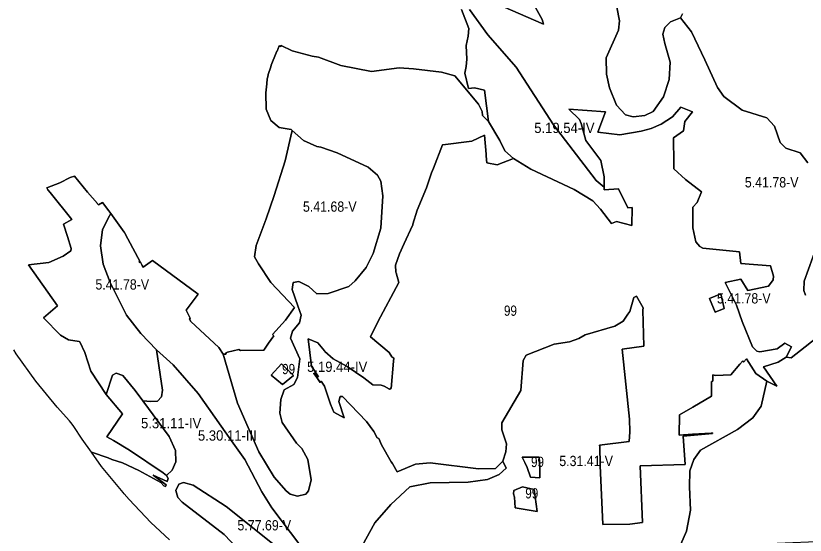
# Model space of a CAD drawing. Extents: x -591496 to -585489, y -1120610 to -1115685.
# Drawn here: x -590587 to -589052, y -1119649 to -1118638 of the extents above; entities that cross this region are included whole.
import ezdxf

# ---------------------------------------------------------------- set-up
doc = ezdxf.new("R2010")
doc.units = 0
doc.header["$LTSCALE"] = 8
doc.layers.add('40', color=7, linetype='Continuous', lineweight=25)
doc.layers.add('41', color=7, linetype='Continuous')

msp = doc.modelspace()

# ---------------------------------------------------------------- linework, layer by layer
at = {"layer": '40'}
for points in [[(-589586, -1118604), (-589563.5, -1118645), (-589561, -1118654.5), (-589684.5, -1118599.5)], [(-589684.5, -1118599.5), (-589561, -1118654.5), (-589563.5, -1118645), (-589586, -1118604)], [(-589720, -1118626), (-589706, -1118663), (-589707.5, -1118678), (-589711.5, -1118696), (-589710, -1118722.5), (-589711.5, -1118736.5), (-589713.5, -1118750), (-589706.5, -1118779.5), (-589695, -1118778.5), (-589675.5, -1118783), (-589667.5, -1118843.5), (-589678.796, -1118832.675), (-589679.511, -1118831.84), (-589680, -1118824.5), (-589687.5, -1118810), (-589733, -1118755), (-589759, -1118748), (-589813.5, -1118741), (-589841.5, -1118739.5), (-589895.5, -1118746.5), (-589955, -1118734.5), (-589998.5, -1118718.5), (-590010.5, -1118716.5), (-590049.5, -1118706), (-590071, -1118696), (-590072.361, -1118697.762), (-590074.98, -1118696.58), (-590079.198, -1118706.609), (-590079.5, -1118707), (-590080.716, -1118710.219), (-590090.81, -1118734.22), (-590090.945, -1118737.295), (-590096.5, -1118752), (-590097.104, -1118756.829), (-590098.58, -1118760.96), (-590098.833, -1118770.662), (-590101, -1118788), (-590100, -1118819.5), (-590091, -1118842), (-590075, -1118855.5), (-590052, -1118859.5), (-590049.613, -1118861.409), (-590050.059, -1118863.857), (-590063.5, -1118920.5), (-590084.5, -1118988), (-590100, -1119033.5), (-590119.5, -1119085), (-590123, -1119107.5), (-590115.5, -1119121), (-590091.5, -1119157), (-590045, -1119206), (-590062.957, -1119230.295), (-590088.22, -1119258.38), (-590085.456, -1119260.734), (-590096, -1119275), (-590104.752, -1119289.08), (-590150.46, -1119289.31), (-590153.81, -1119287.41), (-590175.23, -1119292.91), (-590179.63, -1119294.45), (-590178.088, -1119296.552), (-590184, -1119297), (-590192.5, -1119283.5), (-590247, -1119233), (-590249.332, -1119228.67), (-590248.1, -1119226.71), (-590255.692, -1119211.077), (-590232.5, -1119180), (-590321.5, -1119114.5), (-590339.475, -1119127.272), (-590341.6, -1119124.18), (-590345.08, -1119117.68), (-590346.375, -1119118.505), (-590347.552, -1119116.602), (-590346.15, -1119115.66), (-590349.85, -1119108.74), (-590374.39, -1119062.37), (-590375.21, -1119060.82), (-590376.42, -1119059), (-590402.728, -1119023.107), (-590406.61, -1119017.81)], [(-589705, -1118626), (-589669, -1118675), (-589614, -1118738), (-589541.5, -1118850.5), (-589458, -1118958.5), (-589443, -1118971.5), (-589443, -1118976.5), (-589415, -1118975), (-589396.5, -1119012), (-589388.5, -1119011.5), (-589389, -1119046.5), (-589418.5, -1119038.5), (-589428.5, -1119042.5), (-589450, -1119014.5), (-589465, -1118998.5), (-589501, -1118976), (-589585.5, -1118936.5), (-589619, -1118916), (-589636, -1118901), (-589645.5, -1118880.5), (-589667.5, -1118843.5), (-589675.5, -1118783), (-589695, -1118778.5), (-589706.5, -1118779.5), (-589713.5, -1118750), (-589711.5, -1118736.5), (-589710, -1118722.5), (-589711.5, -1118696), (-589707.5, -1118678), (-589706, -1118663), (-589720, -1118626)], [(-589308, -1118875.5), (-589288.5, -1118862), (-589286, -1118844), (-589271, -1118825), (-589293.5, -1118816), (-589310, -1118835), (-589332, -1118849), (-589351, -1118857.5), (-589370.5, -1118862.5), (-589412, -1118870), (-589455, -1118864.5), (-589440, -1118825), (-589511.5, -1118819.5), (-589491, -1118840), (-589487.5, -1118848), (-589478.5, -1118880.5), (-589449.5, -1118920), (-589442.5, -1118951.5), (-589443, -1118971.5), (-589458, -1118958.5), (-589541.5, -1118850.5), (-589614, -1118738), (-589669, -1118675), (-589705, -1118626)], [(-589290, -1118634), (-589294.5, -1118642), (-589313.5, -1118650), (-589325, -1118660.5), (-589328.5, -1118674), (-589324.5, -1118692), (-589314.5, -1118728), (-589316.5, -1118762), (-589327.5, -1118795.5), (-589347.5, -1118824.5), (-589363.5, -1118832), (-589386.5, -1118834.5), (-589401, -1118830.5), (-589418.5, -1118812), (-589432.5, -1118778.5), (-589438.5, -1118751.5), (-589439, -1118720), (-589415, -1118666), (-589413, -1118648), (-589418, -1118621)], [(-589418, -1118621), (-589413, -1118648), (-589415, -1118666), (-589439, -1118720), (-589438.5, -1118751.5), (-589432.5, -1118778.5), (-589418.5, -1118812), (-589401, -1118830.5), (-589386.5, -1118834.5), (-589363.5, -1118832), (-589347.5, -1118824.5), (-589327.5, -1118795.5), (-589316.5, -1118762), (-589314.5, -1118728), (-589324.5, -1118692), (-589328.5, -1118674), (-589325, -1118660.5), (-589313.5, -1118650), (-589294.5, -1118642)], [(-589046.5, -1118924.5), (-589061.5, -1118904.5), (-589089, -1118895.5), (-589100, -1118884.5), (-589111.5, -1118853), (-589126.5, -1118836.5), (-589174.5, -1118822), (-589210, -1118795), (-589222.5, -1118777.5), (-589247, -1118723.5), (-589273, -1118669.5), (-589294.5, -1118642), (-589290, -1118634)], [(-589294.5, -1118642), (-589273, -1118669.5), (-589247, -1118723.5), (-589222.5, -1118777.5), (-589210, -1118795), (-589174.5, -1118822), (-589126.5, -1118836.5), (-589111.5, -1118853), (-589100, -1118884.5), (-589089, -1118895.5), (-589061.5, -1118904.5), (-589046.5, -1118924.5)], [(-590404, -1119157.5), (-590417.5, -1119121.5), (-590422.5, -1119085.5), (-590419, -1119054), (-590405, -1119027.5), (-590402.728, -1119023.107), (-590376.42, -1119059), (-590375.21, -1119060.82), (-590374.39, -1119062.37), (-590349.85, -1119108.74), (-590346.15, -1119115.66), (-590347.552, -1119116.602), (-590346.375, -1119118.505), (-590345.08, -1119117.68), (-590341.6, -1119124.18), (-590339.475, -1119127.272), (-590321.5, -1119114.5), (-590232.5, -1119180), (-590255.692, -1119211.077), (-590248.1, -1119226.71), (-590249.332, -1119228.67), (-590247, -1119233), (-590192.5, -1119283.5), (-590184, -1119297), (-590156, -1119392), (-590114.5, -1119486.5), (-590085, -1119536), (-590061.5, -1119563), (-590053.5, -1119569.5), (-590039.5, -1119573), (-590023, -1119569.5), (-590018, -1119563), (-590013, -1119541.5), (-590019.5, -1119501.5), (-590031, -1119480.5), (-590041.5, -1119470), (-590069.5, -1119429.5), (-590073.5, -1119411.5), (-590072, -1119385), (-590065.5, -1119366), (-590046.5, -1119355.5), (-590039.5, -1119342), (-590034.5, -1119306), (-590053, -1119265.5), (-590049, -1119252), (-590035.5, -1119236), (-590032.5, -1119220.5), (-590038.5, -1119202.5), (-590049.5, -1119171), (-590047.5, -1119157.5), (-590036.5, -1119155), (-590017, -1119165), (-590002, -1119179.5), (-589979.5, -1119178.5), (-589939.5, -1119165), (-589927, -1119154), (-589906, -1119128), (-589892, -1119101), (-589877, -1119051.5), (-589873.5, -1118988.5), (-589877, -1118960), (-589883.5, -1118948.5), (-589902, -1118933), (-589962.5, -1118904.5), (-589994, -1118894), (-590002, -1118892.5), (-590027.5, -1118881), (-590049.5, -1118861.5), (-590049.613, -1118861.409), (-590052, -1118859.5), (-590075, -1118855.5), (-590091, -1118842), (-590100, -1118819.5), (-590101, -1118788), (-590098.833, -1118770.662), (-590098.58, -1118760.96), (-590097.104, -1118756.829), (-590096.5, -1118752), (-590090.945, -1118737.295), (-590090.81, -1118734.22), (-590080.716, -1118710.219), (-590079.5, -1118707), (-590079.198, -1118706.609), (-590074.98, -1118696.58), (-590072.361, -1118697.762), (-590071, -1118696), (-590049.5, -1118706), (-590010.5, -1118716.5), (-589998.5, -1118718.5), (-589955, -1118734.5), (-589895.5, -1118746.5), (-589841.5, -1118739.5), (-589813.5, -1118741), (-589759, -1118748), (-589733, -1118755), (-589687.5, -1118810), (-589680, -1118824.5), (-589679.511, -1118831.84), (-589678.796, -1118832.675), (-589667.5, -1118843.5)], [(-589857, -1119363.5), (-589852.796, -1119310.255), (-589852.18, -1119304.74), (-589855.544, -1119301.845), (-589861, -1119293.5), (-589897.347, -1119262.63), (-589883.35, -1119234.06), (-589841.98, -1119156.96), (-589847.625, -1119138.5), (-589848, -1119137), (-589849, -1119123.5), (-589840.817, -1119101.358), (-589831.512, -1119081.087), (-589815.5, -1119046.5), (-589815.266, -1119045.693), (-589814.87, -1119044.83), (-589814.675, -1119043.651), (-589806.701, -1119016.131), (-589788.32, -1118972.91), (-589778.802, -1118943.68), (-589775, -1118934.5), (-589757.026, -1118889.067), (-589756.725, -1118888.966), (-589700.5, -1118882), (-589675.5, -1118870.5), (-589672.379, -1118907.607), (-589671.95, -1118921.28), (-589671.222, -1118921.356), (-589671, -1118924), (-589651, -1118928), (-589619, -1118916), (-589585.5, -1118936.5), (-589501, -1118976), (-589465, -1118998.5), (-589450, -1119014.5), (-589428.5, -1119042.5), (-589418.5, -1119038.5), (-589389, -1119046.5), (-589388.5, -1119011.5), (-589396.5, -1119012), (-589415, -1118975), (-589443, -1118976.5), (-589443, -1118971.5), (-589442.5, -1118951.5), (-589449.5, -1118920), (-589478.5, -1118880.5), (-589487.5, -1118848), (-589491, -1118840), (-589511.5, -1118819.5), (-589440, -1118825), (-589455, -1118864.5), (-589412, -1118870), (-589370.5, -1118862.5), (-589351, -1118857.5), (-589332, -1118849), (-589310, -1118835), (-589293.5, -1118816), (-589271, -1118825), (-589286, -1118844), (-589288.5, -1118862), (-589308, -1118875.5), (-589307, -1118925), (-589307, -1118936), (-589284.5, -1118956.5), (-589253.5, -1118981), (-589262, -1119001.5), (-589270, -1119010.5), (-589270.5, -1119051), (-589264.5, -1119078), (-589256.5, -1119087), (-589251, -1119090.5), (-589179.5, -1119097.5), (-589177, -1119120), (-589119, -1119124.5), (-589113.5, -1119145), (-589114, -1119152), (-589123, -1119164.5), (-589163.5, -1119173), (-589177, -1119151), (-589207, -1119157.5), (-589185.5, -1119201.5), (-589174, -1119233), (-589154, -1119282.5), (-589146, -1119291), (-589140, -1119292), (-589106, -1119286), (-589091.5, -1119275.5), (-589078.5, -1119282.5), (-589088.5, -1119302.5)], [(-589667.5, -1118843.5), (-589645.5, -1118880.5), (-589636, -1118901), (-589619, -1118916), (-589651, -1118928), (-589671, -1118924), (-589671.222, -1118921.356), (-589671.95, -1118921.28), (-589672.379, -1118907.607), (-589675.5, -1118870.5), (-589700.5, -1118882), (-589756.725, -1118888.966), (-589757.026, -1118889.067), (-589775, -1118934.5), (-589778.802, -1118943.68), (-589788.32, -1118972.91), (-589806.701, -1119016.131), (-589814.675, -1119043.651), (-589814.87, -1119044.83), (-589815.266, -1119045.693), (-589815.5, -1119046.5), (-589831.512, -1119081.087), (-589840.817, -1119101.358), (-589849, -1119123.5), (-589848, -1119137), (-589847.625, -1119138.5), (-589841.98, -1119156.96), (-589883.35, -1119234.06), (-589897.347, -1119262.63), (-589861, -1119293.5), (-589855.544, -1119301.845), (-589852.18, -1119304.74), (-589852.796, -1119310.255), (-589857, -1119363.5), (-589858.685, -1119362.938), (-589858.91, -1119364.95), (-589860.57, -1119364.94), (-589871.048, -1119358.817), (-589876.863, -1119356.879), (-589892.92, -1119356.33), (-589909.98, -1119342.589), (-589942.708, -1119320.455), (-589970.18, -1119305.68), (-589986.03, -1119291.28), (-589986.049, -1119291.143), (-589987, -1119290.5), (-590000, -1119274.5), (-590018.53, -1119267.147), (-590012.06, -1119320.12), (-589998.55, -1119340.86), (-590007.51, -1119333.92), (-590007.886, -1119334.386), (-590001.5, -1119342), (-589995.49, -1119351.533), (-589993.21, -1119349.05), (-589986.79, -1119358.9), (-589977.39, -1119388.225), (-589975, -1119394), (-589968.5, -1119409.5), (-589948.5, -1119420.5), (-589959, -1119389), (-589956.5, -1119379), (-589951.5, -1119379), (-589905, -1119428), (-589891, -1119447.5), (-589884.107, -1119459.391), (-589881.2, -1119461), (-589876.156, -1119473.11), (-589857.084, -1119506.015), (-589854.65, -1119509.64), (-589854.17, -1119511.041), (-589845.5, -1119526), (-589809.5, -1119511), (-589781, -1119508), (-589687, -1119520), (-589654, -1119519), (-589640, -1119505), (-589633.5, -1119518.5), (-589647, -1119531), (-589670, -1119540.5), (-589707, -1119546), (-589781, -1119547), (-589820.5, -1119555), (-589858, -1119589), (-589889, -1119625), (-589913.5, -1119670)], [(-589012, -1119251), (-589079, -1119304), (-589088.5, -1119302.5), (-589078.5, -1119282.5), (-589091.5, -1119275.5), (-589106, -1119286), (-589140, -1119292), (-589146, -1119291), (-589154, -1119282.5), (-589174, -1119233), (-589185.5, -1119201.5), (-589207, -1119157.5), (-589177, -1119151), (-589163.5, -1119173), (-589123, -1119164.5), (-589114, -1119152), (-589113.5, -1119145), (-589119, -1119124.5), (-589177, -1119120), (-589179.5, -1119097.5), (-589251, -1119090.5), (-589256.5, -1119087), (-589264.5, -1119078), (-589270.5, -1119051), (-589270, -1119010.5), (-589262, -1119001.5), (-589253.5, -1118981), (-589284.5, -1118956.5), (-589307, -1118936), (-589307, -1118925), (-589308, -1118875.5)], [(-590406.61, -1119017.81), (-590418.78, -1119001.7), (-590426.522, -1119005.978), (-590429.028, -1119003.472), (-590428.57, -1119003.21), (-590447.617, -1118981.388), (-590473, -1118950.5), (-590481.5, -1118952.5), (-590501.731, -1118963.075), (-590510.05, -1118966.23), (-590527.08, -1118972.62), (-590524.91, -1118976.64), (-590520.401, -1118981.955), (-590478.665, -1119034.791), (-590494.88, -1119043.75), (-590486.533, -1119067.38), (-590480, -1119091), (-590480.5, -1119095.5), (-590495.5, -1119106), (-590523, -1119118), (-590563, -1119123), (-590506, -1119202.5), (-590533.5, -1119226), (-590500.5, -1119259.5), (-590485, -1119269), (-590464.363, -1119271.814), (-590462.597, -1119272.867), (-590453, -1119293.5), (-590441.5, -1119329.5), (-590411.5, -1119375), (-590380, -1119412.5), (-590410, -1119457.5), (-590397.5, -1119464.5), (-590366, -1119483.5), (-590300.5, -1119527.5), (-590294, -1119533), (-590291, -1119538.5), (-590292.901, -1119544.585), (-590320.08, -1119532.32), (-590294.973, -1119551.214), (-590296, -1119554.5), (-590299.282, -1119552.785), (-590304.95, -1119546.61), (-590348.36, -1119523.25), (-590380.08, -1119508.2), (-590400.352, -1119501.759), (-590407.5, -1119498.5), (-590440.181, -1119487.607), (-590458.48, -1119462.07), (-590474.227, -1119437.746), (-590477.743, -1119433.191), (-590483.035, -1119426.232), (-590506.88, -1119399.996), (-590548.393, -1119349.411), (-590586.51, -1119296.22), (-590591.55, -1119288.115)], [(-589028.5, -1119084.5), (-589053.5, -1119154.5), (-589054.5, -1119172.5), (-589051, -1119182)], [(-589051, -1119182), (-589054.5, -1119172.5), (-589053.5, -1119154.5), (-589028.5, -1119084.5)], [(-590035, -1119668), (-590089, -1119596), (-590108.5, -1119564.5), (-590141.5, -1119501.5), (-590167.5, -1119465.5), (-590232.5, -1119373), (-590281, -1119317.5), (-590313.5, -1119288), (-590344, -1119256.5), (-590372, -1119220.5), (-590404, -1119157.5)], [(-589088.5, -1119302.5), (-589104, -1119312), (-589132.5, -1119321.5), (-589107, -1119359), (-589126.5, -1119349.5), (-589147.5, -1119334.5), (-589165.5, -1119305.5), (-589171.64, -1119312.057), (-589173.09, -1119309.83), (-589178.78, -1119316.45), (-589196.503, -1119337.049), (-589226, -1119338), (-589231.5, -1119337), (-589231.553, -1119349.125), (-589233.82, -1119349.83), (-589234.1, -1119378.75), (-589270.43, -1119399.89), (-589296.34, -1119414.97), (-589296.52, -1119454.44), (-589270.94, -1119452.55), (-589234.8, -1119450.31), (-589231.996, -1119450.106), (-589232, -1119451), (-589289, -1119456.5), (-589285, -1119511.5), (-589372.5, -1119514), (-589368, -1119624.5), (-589393, -1119627.5), (-589445.5, -1119628), (-589450.339, -1119513.362), (-589451.28, -1119474.97), (-589451.954, -1119475.086), (-589452, -1119474), (-589394, -1119466.5), (-589393, -1119448), (-589393.5, -1119423.5), (-589407.5, -1119287), (-589365.5, -1119281), (-589367.5, -1119211), (-589367, -1119206.5), (-589379.5, -1119183.5), (-589385, -1119186.5), (-589392.5, -1119213.5), (-589396.5, -1119219), (-589405.5, -1119232.5), (-589422, -1119242), (-589479.5, -1119259), (-589492, -1119266.5), (-589510, -1119272.5), (-589540, -1119277.5), (-589594.5, -1119298.5), (-589600, -1119309), (-589605, -1119367.5), (-589642, -1119430.5), (-589642, -1119444), (-589632.5, -1119471), (-589634, -1119486.5), (-589640, -1119505), (-589654, -1119519), (-589687, -1119520), (-589781, -1119508), (-589809.5, -1119511), (-589845.5, -1119526), (-589854.17, -1119511.041), (-589854.65, -1119509.64), (-589857.084, -1119506.015), (-589876.156, -1119473.11), (-589881.2, -1119461), (-589884.107, -1119459.391), (-589891, -1119447.5), (-589905, -1119428), (-589951.5, -1119379), (-589956.5, -1119379), (-589959, -1119389), (-589948.5, -1119420.5), (-589968.5, -1119409.5), (-589975, -1119394), (-589977.39, -1119388.225), (-589986.79, -1119358.9), (-589993.21, -1119349.05), (-589995.49, -1119351.533), (-590001.5, -1119342), (-590007.886, -1119334.386), (-590007.51, -1119333.92), (-589998.55, -1119340.86), (-590012.06, -1119320.12), (-590018.53, -1119267.147), (-590000, -1119274.5), (-589987, -1119290.5), (-589986.049, -1119291.143), (-589986.03, -1119291.28), (-589970.18, -1119305.68), (-589942.708, -1119320.455), (-589909.98, -1119342.589), (-589892.92, -1119356.33), (-589876.863, -1119356.879), (-589871.048, -1119358.817), (-589860.57, -1119364.94), (-589858.91, -1119364.95), (-589858.685, -1119362.938), (-589857, -1119363.5)], [(-589913.5, -1119670), (-589889, -1119625), (-589858, -1119589), (-589820.5, -1119555), (-589781, -1119547), (-589707, -1119546), (-589670, -1119540.5), (-589647, -1119531), (-589633.5, -1119518.5), (-589640, -1119505), (-589634, -1119486.5), (-589632.5, -1119471), (-589642, -1119444), (-589642, -1119430.5), (-589605, -1119367.5), (-589600, -1119309), (-589594.5, -1119298.5), (-589540, -1119277.5), (-589510, -1119272.5), (-589492, -1119266.5), (-589479.5, -1119259), (-589422, -1119242), (-589405.5, -1119232.5), (-589396.5, -1119219), (-589392.5, -1119213.5), (-589385, -1119186.5), (-589379.5, -1119183.5), (-589367, -1119206.5), (-589367.5, -1119211), (-589365.5, -1119281), (-589407.5, -1119287), (-589393.5, -1119423.5), (-589393, -1119448), (-589394, -1119466.5), (-589452, -1119474), (-589451.954, -1119475.086), (-589451.28, -1119474.97), (-589450.339, -1119513.362), (-589445.5, -1119628), (-589393, -1119627.5), (-589368, -1119624.5), (-589372.5, -1119514), (-589285, -1119511.5), (-589289, -1119456.5), (-589232, -1119451), (-589231.996, -1119450.106), (-589234.8, -1119450.31), (-589270.94, -1119452.55), (-589296.52, -1119454.44), (-589296.34, -1119414.97), (-589270.43, -1119399.89), (-589234.1, -1119378.75), (-589233.82, -1119349.83), (-589231.553, -1119349.125), (-589231.5, -1119337), (-589226, -1119338), (-589196.503, -1119337.049), (-589178.78, -1119316.45), (-589173.09, -1119309.83), (-589171.64, -1119312.057), (-589165.5, -1119305.5), (-589147.5, -1119334.5), (-589126.5, -1119349.5), (-589137.5, -1119398), (-589153.5, -1119420.5), (-589183.5, -1119443), (-589255, -1119483.5), (-589268.5, -1119501.5), (-589276, -1119524), (-589276.5, -1119555), (-589274.5, -1119600.5), (-589282.5, -1119641), (-589304.495, -1119691.988)], [(-588953.5, -1119659), (-589167, -1119667.5), (-589213, -1119678), (-589246, -1119686.5), (-589270.5, -1119690), (-589304.495, -1119691.988), (-589282.5, -1119641), (-589274.5, -1119600.5), (-589276.5, -1119555), (-589276, -1119524), (-589268.5, -1119501.5), (-589255, -1119483.5), (-589183.5, -1119443), (-589153.5, -1119420.5), (-589137.5, -1119398), (-589126.5, -1119349.5), (-589107, -1119359), (-589132.5, -1119321.5), (-589104, -1119312), (-589088.5, -1119302.5), (-589079, -1119304), (-589012, -1119251)], [(-590288.534, -1119658.177), (-590324.527, -1119624.467), (-590366.996, -1119579.278), (-590376.586, -1119568.418), (-590378.85, -1119565.846), (-590420.363, -1119515.261), (-590440.181, -1119487.607), (-590407.5, -1119498.5), (-590400.352, -1119501.759), (-590380.08, -1119508.2), (-590348.36, -1119523.25), (-590304.95, -1119546.61), (-590299.282, -1119552.785), (-590296, -1119554.5), (-590294.973, -1119551.214), (-590320.08, -1119532.32), (-590292.901, -1119544.585), (-590291, -1119538.5), (-590294, -1119533), (-590283.5, -1119522.5), (-590276, -1119506.5), (-590277, -1119484), (-590289, -1119457), (-590340.59, -1119387.567), (-590324.5, -1119389), (-590311.5, -1119388), (-590304, -1119380), (-590302, -1119366.5), (-590313.5, -1119288), (-590281, -1119317.5), (-590232.5, -1119373), (-590167.5, -1119465.5), (-590141.5, -1119501.5), (-590108.5, -1119564.5), (-590089, -1119596), (-590035, -1119668)], [(-590088, -1119665.5), (-590178, -1119593.5), (-590242.5, -1119551.5), (-590261, -1119546.5), (-590270, -1119549.5), (-590276, -1119562), (-590272.5, -1119575.5), (-590264, -1119585), (-590182, -1119647.5), (-590157, -1119674.5)]]:
    msp.add_lwpolyline(points, dxfattribs=at)
for points in [[(-590184, -1119297), (-590178.088, -1119296.552), (-590179.63, -1119294.45), (-590175.23, -1119292.91), (-590153.81, -1119287.41), (-590150.46, -1119289.31), (-590104.752, -1119289.08), (-590096, -1119275), (-590085.456, -1119260.734), (-590088.22, -1119258.38), (-590062.957, -1119230.295), (-590045, -1119206), (-590091.5, -1119157), (-590115.5, -1119121), (-590123, -1119107.5), (-590119.5, -1119085), (-590100, -1119033.5), (-590084.5, -1118988), (-590063.5, -1118920.5), (-590050.059, -1118863.857), (-590049.613, -1118861.409), (-590049.5, -1118861.5), (-590027.5, -1118881), (-590002, -1118892.5), (-589994, -1118894), (-589962.5, -1118904.5), (-589902, -1118933), (-589883.5, -1118948.5), (-589877, -1118960), (-589873.5, -1118988.5), (-589877, -1119051.5), (-589892, -1119101), (-589906, -1119128), (-589927, -1119154), (-589939.5, -1119165), (-589979.5, -1119178.5), (-590002, -1119179.5), (-590017, -1119165), (-590036.5, -1119155), (-590047.5, -1119157.5), (-590049.5, -1119171), (-590038.5, -1119202.5), (-590032.5, -1119220.5), (-590035.5, -1119236), (-590049, -1119252), (-590053, -1119265.5), (-590034.5, -1119306), (-590039.5, -1119342), (-590046.5, -1119355.5), (-590065.5, -1119366), (-590072, -1119385), (-590073.5, -1119411.5), (-590069.5, -1119429.5), (-590041.5, -1119470), (-590031, -1119480.5), (-590019.5, -1119501.5), (-590013, -1119541.5), (-590018, -1119563), (-590023, -1119569.5), (-590039.5, -1119573), (-590053.5, -1119569.5), (-590061.5, -1119563), (-590085, -1119536), (-590114.5, -1119486.5), (-590156, -1119392)], [(-590402.728, -1119023.107), (-590405, -1119027.5), (-590419, -1119054), (-590422.5, -1119085.5), (-590417.5, -1119121.5), (-590404, -1119157.5), (-590372, -1119220.5), (-590344, -1119256.5), (-590313.5, -1119288), (-590302, -1119366.5), (-590304, -1119380), (-590311.5, -1119388), (-590324.5, -1119389), (-590340.59, -1119387.567), (-590355.5, -1119367.5), (-590379, -1119338), (-590392, -1119333.5), (-590399.5, -1119337.5), (-590411.5, -1119375), (-590441.5, -1119329.5), (-590453, -1119293.5), (-590462.597, -1119272.867), (-590464.363, -1119271.814), (-590485, -1119269), (-590500.5, -1119259.5), (-590533.5, -1119226), (-590506, -1119202.5), (-590563, -1119123), (-590523, -1119118), (-590495.5, -1119106), (-590480.5, -1119095.5), (-590480, -1119091), (-590486.533, -1119067.38), (-590494.88, -1119043.75), (-590478.665, -1119034.791), (-590520.401, -1118981.955), (-590524.91, -1118976.64), (-590527.08, -1118972.62), (-590510.05, -1118966.23), (-590501.731, -1118963.075), (-590481.5, -1118952.5), (-590473, -1118950.5), (-590447.617, -1118981.388), (-590428.57, -1119003.21), (-590429.028, -1119003.472), (-590426.522, -1119005.978), (-590418.78, -1119001.7), (-590406.61, -1119017.81)], [(-589209, -1119208), (-589215.5, -1119179.5), (-589237.5, -1119188), (-589227, -1119215)], [(-589209, -1119208), (-589227, -1119215), (-589237.5, -1119188), (-589215.5, -1119179.5)], [(-590047, -1119338.5), (-590068.327, -1119355.726), (-590090.54, -1119337.84), (-590070.791, -1119315.642)], [(-590047, -1119338.5), (-590070.791, -1119315.642), (-590090.54, -1119337.84), (-590068.327, -1119355.726)], [(-590340.59, -1119387.567), (-590289, -1119457), (-590277, -1119484), (-590276, -1119506.5), (-590283.5, -1119522.5), (-590294, -1119533), (-590300.5, -1119527.5), (-590366, -1119483.5), (-590397.5, -1119464.5), (-590410, -1119457.5), (-590380, -1119412.5), (-590411.5, -1119375), (-590399.5, -1119337.5), (-590392, -1119333.5), (-590379, -1119338), (-590355.5, -1119367.5)], [(-589568.09, -1119517.13), (-589567.57, -1119537.53), (-589586.104, -1119535.837), (-589592.5, -1119517.5), (-589597, -1119507.5), (-589602.5, -1119497), (-589569.5, -1119497), (-589568.062, -1119517.125)], [(-589568.09, -1119517.13), (-589568.062, -1119517.125), (-589569.5, -1119497), (-589602.5, -1119497), (-589597, -1119507.5), (-589592.5, -1119517.5), (-589586.104, -1119535.837), (-589567.57, -1119537.53)], [(-590063.5, -1119719), (-590078, -1119728), (-590102.5, -1119733), (-590122.567, -1119727.234), (-590157, -1119674.5), (-590182, -1119647.5), (-590264, -1119585), (-590272.5, -1119575.5), (-590276, -1119562), (-590270, -1119549.5), (-590261, -1119546.5), (-590242.5, -1119551.5), (-590178, -1119593.5), (-590088, -1119665.5), (-590067, -1119692.5), (-590062.5, -1119706)], [(-589579, -1119560), (-589573, -1119603), (-589616, -1119595.5), (-589617, -1119575), (-589619.389, -1119568.63), (-589618.784, -1119561.914), (-589601.5, -1119555)], [(-589579, -1119560), (-589601.5, -1119555), (-589618.784, -1119561.914), (-589619.389, -1119568.63), (-589617, -1119575), (-589616, -1119595.5), (-589573, -1119603)]]:
    msp.add_lwpolyline(points, close=True, dxfattribs=at)

# ---------------------------------------------------------------- texts
at = {"layer": '41'}
for s, width, p in [('5.19.54-IV', 0.95, (-589578.75, -1118866.188)), ('5.41.78-V', 0.9, (-589169, -1118972.125)), ('5.41.68-V', 0.9, (-590028.75, -1119019.438)), ('5.41.78-V', 0.9, (-590432.5, -1119170.938)), ('5.41.78-V', 0.9, (-589223.25, -1119198)), ('99', 0.85, (-589637.688, -1119222)), ('5.19.44-IV', 0.95, (-590020.75, -1119331.188)), ('99', 0.85, (-590069.281, -1119335.625)), ('5.31.11-IV', 0.95, (-590343.75, -1119440.938)), ('5.30.11-III', 0.95, (-590233.063, -1119465)), ('5.31.41-V', 0.9, (-589530, -1119514.563)), ('99', 0.85, (-589585.063, -1119516.438)), ('99', 0.85, (-589596.188, -1119577.563)), ('5.77.69-V', 0.9, (-590156.188, -1119639.75))]:
    msp.add_text(s, height=20, dxfattribs=dict(at, width=width)).set_placement(p)

doc.saveas('drawing.dxf')
